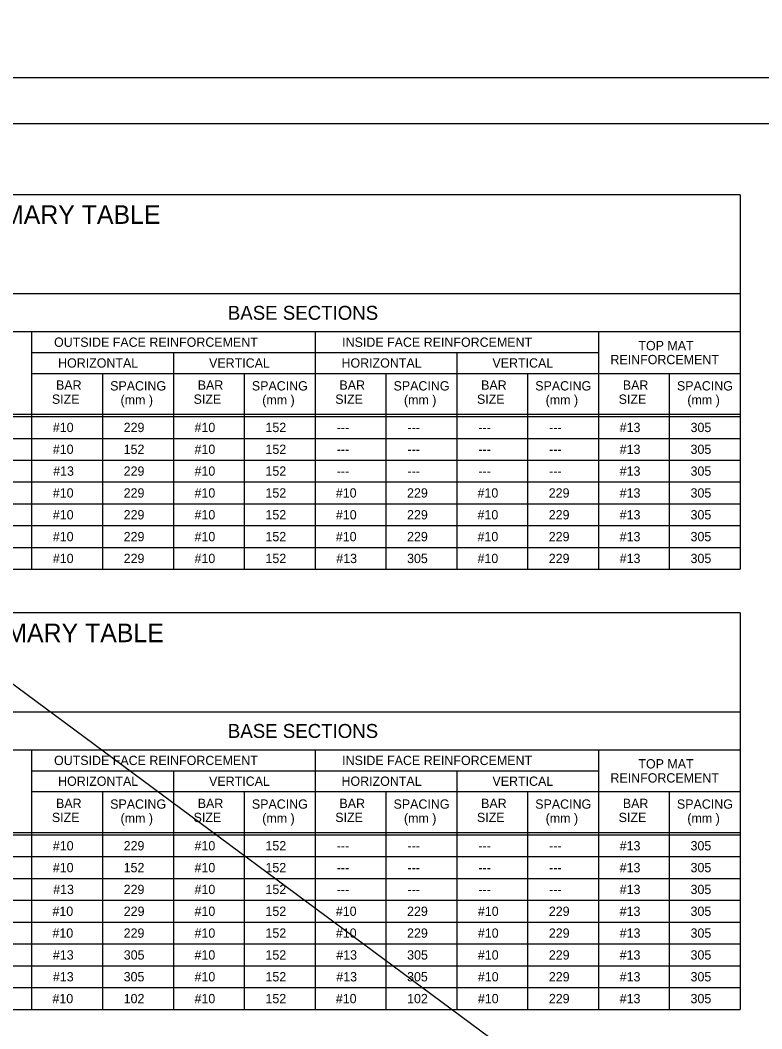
# Model space of a CAD drawing. Extents: x -6420 to 49575, y -4552 to 11624.
# Drawn here: x 35901 to 36686, y 4771 to 5838 of the extents above; entities that cross this region are included whole.
import ezdxf

# ---------------------------------------------------------------- set-up
doc = ezdxf.new("R2010")
doc.units = 0
doc.layers.add('1', color=7, linetype='Continuous')
doc.layers.add('4', color=7, linetype='Continuous')

msp = doc.modelspace()

# ---------------------------------------------------------------- linework, layer by layer
at = {"layer": '1'}
for p, q in [((34295.4, 6319.6), (48971.6, -4552.2)), ((36663.5, 5653.2), (34868.5, 5653.2)), ((36663.5, 5653.2), (36663.5, 5256.9)), ((36663.5, 5548.2), (34868.5, 5548.2)), ((36663.5, 5508.2), (35088.5, 5508.2)), ((35913.5, 5508.2), (35913.5, 5256.9)), ((36213.5, 5508.2), (36213.5, 5256.9)), ((36513.5, 5508.2), (36513.5, 5256.9)), ((35913.5, 5486.2), (36213.5, 5486.2)), ((36063.5, 5486.2), (36063.5, 5256.9)), ((36213.5, 5486.2), (36513.5, 5486.2)), ((36363.5, 5486.2), (36363.5, 5256.9)), ((35913.5, 5464.2), (36213.5, 5464.2)), ((35988.5, 5464.2), (35988.5, 5256.9)), ((36138.5, 5464.2), (36138.5, 5256.9)), ((36213.5, 5464.2), (36663.5, 5464.2)), ((36288.5, 5464.2), (36288.5, 5256.9)), ((36438.5, 5464.2), (36438.5, 5256.9)), ((36588.5, 5464.2), (36588.5, 5256.9)), ((34868.5, 5421), (36663.5, 5421)), ((34868.5, 5418.5), (36663.5, 5418.5)), ((34868.5, 5395.4), (36663.5, 5395.4)), ((34868.5, 5372.4), (36663.5, 5372.4)), ((34868.5, 5349.3), (36663.5, 5349.3)), ((34868.5, 5326.2), (36663.5, 5326.2)), ((34868.5, 5303.1), (36663.5, 5303.1)), ((34868.5, 5280), (36663.5, 5280)), ((34868.5, 5256.9), (36663.5, 5256.9)), ((36663.5, 5210.7), (34868.5, 5210.7)), ((36663.5, 5210.7), (36663.5, 4791.2)), ((36663.5, 5105.7), (34868.5, 5105.7)), ((36663.5, 5065.7), (35088.5, 5065.7)), ((35913.5, 5065.7), (35913.5, 4791.2)), ((36213.5, 5065.7), (36213.5, 4791.2)), ((36513.5, 5065.7), (36513.5, 4791.2)), ((35913.5, 5043.7), (36213.5, 5043.7)), ((36063.5, 5043.7), (36063.5, 4791.2)), ((36213.5, 5043.7), (36513.5, 5043.7)), ((36363.5, 5043.7), (36363.5, 4791.2)), ((35913.5, 5021.7), (36213.5, 5021.7)), ((35988.5, 5021.7), (35988.5, 4791.2)), ((36138.5, 5021.7), (36138.5, 4791.2)), ((36213.5, 5021.7), (36663.5, 5021.7)), ((36288.5, 5021.7), (36288.5, 4791.2)), ((36438.5, 5021.7), (36438.5, 4791.2)), ((36588.5, 5021.7), (36588.5, 4791.2)), ((34868.5, 4978.4), (36663.5, 4978.4)), ((34868.5, 4976), (36663.5, 4976)), ((34868.5, 4952.9), (36663.5, 4952.9)), ((34868.5, 4929.8), (36663.5, 4929.8)), ((34868.5, 4906.7), (36663.5, 4906.7)), ((34868.5, 4883.6), (36663.5, 4883.6)), ((34868.5, 4860.5), (36663.5, 4860.5)), ((34868.5, 4837.4), (36663.5, 4837.4)), ((34868.5, 4814.3), (36663.5, 4814.3)), ((34868.5, 4791.2), (36663.5, 4791.2))]:
    msp.add_line(p, q, dxfattribs=at)
msp.add_lwpolyline([(37372.3, 3877.8), (37372.3, 5728.2), (34793.5, 5728.2), (34793.5, 3877.8), (37372.3, 3877.8), (37372.3, 3964.3), (36716.1, 3964.3), (36716.1, 4176.5), (37372.3, 4176.5), (37372.3, 4271.5), (36716.1, 4271.5), (36716.1, 3877.8), (36974.7, 3877.8), (36974.7, 3964.3), (36974.7, 3877.8), (37227.3, 3877.8), (37227.3, 3964.3), (37227.3, 3923.9), (37372.3, 3923.9)], dxfattribs=at)
at = {"layer": '4'}
msp.add_lwpolyline([(34665.6, 5777.4), (37424.8, 5777.4), (37424.8, 3828.6), (34665.6, 3828.6)], close=True, dxfattribs=at)

# ---------------------------------------------------------------- texts
at = {"layer": '1'}
for s, height, p in [('CAST-IN-PLACE CONCRETE INLET BOX SUMMARY TABLE', 19.685, (35317.1, 5622.4)), ('BASE SECTIONS', 14.764, (36121.2, 5520.9)), ('OUTSIDE FACE REINFORCEMENT', 9.843, (35937.2, 5492.3)), ('INSIDE FACE REINFORCEMENT', 9.843, (36242.2, 5492.3)), ('TOP MAT', 9.84, (36555.8, 5488.7)), ('HORIZONTAL', 9.84, (35941.5, 5470.3)), ('VERTICAL', 9.84, (36101.3, 5470.3)), ('HORIZONTAL', 9.84, (36241.5, 5470.3)), ('VERTICAL', 9.84, (36401.3, 5470.3)), ('REINFORCEMENT', 9.843, (36526.2, 5473.9)), ('BAR', 9.84, (35939.3, 5446.9)), ('SPACING', 9.84, (35996.6, 5446.1)), ('BAR', 9.84, (36089.3, 5446.9)), ('SPACING', 9.84, (36146.6, 5446.1)), ('BAR', 9.84, (36239.3, 5446.9)), ('SPACING', 9.84, (36296.6, 5446.1)), ('BAR', 9.84, (36389.3, 5446.9)), ('SPACING', 9.84, (36446.6, 5446.1)), ('BAR', 9.84, (36539.3, 5446.9)), ('SPACING', 9.84, (36596.6, 5446.1)), ('SIZE', 9.84, (35934.9, 5432)), ('(mm )', 9.84, (36007.6, 5431.3)), ('SIZE', 9.84, (36084.9, 5432)), ('(mm )', 9.84, (36157.6, 5431.3)), ('SIZE', 9.84, (36234.9, 5432)), ('(mm )', 9.84, (36307.6, 5431.3)), ('SIZE', 9.84, (36384.9, 5432)), ('(mm )', 9.84, (36457.6, 5431.3)), ('SIZE', 9.84, (36534.9, 5432)), ('(mm )', 9.84, (36607.6, 5431.3)), ('#10', 9.84, (35935.9, 5402.1)), ('229', 9.84, (36010.9, 5402.1)), ('#10', 9.84, (36085.9, 5402.1)), ('152', 9.84, (36161, 5402.1)), ('#13', 9.84, (36536, 5402.1)), ('305', 9.84, (36611, 5402.1)), ('---', 9.84, (36236.4, 5402.1)), ('---', 9.84, (36311.4, 5402.1)), ('---', 9.84, (36386.4, 5402.1)), ('---', 9.84, (36461.4, 5402.1)), ('#10', 9.84, (35935.9, 5379)), ('152', 9.84, (36010.9, 5379)), ('#10', 9.84, (36085.9, 5379)), ('152', 9.84, (36161, 5379)), ('---', 9.84, (36236.4, 5379)), ('---', 9.84, (36311.4, 5379)), ('---', 9.84, (36386.4, 5379)), ('---', 9.84, (36461.4, 5379)), ('#13', 9.84, (36536, 5379)), ('305', 9.84, (36611, 5379)), ('#13', 9.84, (35936.3, 5355.9)), ('229', 9.84, (36010.9, 5355.9)), ('#10', 9.84, (36085.9, 5355.9)), ('152', 9.84, (36161, 5355.9)), ('---', 9.84, (36236.4, 5355.9)), ('---', 9.84, (36311.4, 5355.9)), ('---', 9.84, (36386.4, 5355.9)), ('---', 9.84, (36461.4, 5355.9)), ('#13', 9.84, (36536, 5355.9)), ('305', 9.84, (36611, 5355.9)), ('#10', 9.84, (35935.9, 5332.8)), ('229', 9.84, (36010.9, 5332.8)), ('#10', 9.84, (36085.9, 5332.8)), ('152', 9.84, (36161, 5332.8)), ('#10', 9.84, (36235.5, 5332.8)), ('229', 9.84, (36310.9, 5332.8)), ('#10', 9.84, (36385.5, 5332.8)), ('229', 9.84, (36460.9, 5332.8)), ('#13', 9.84, (36536, 5332.8)), ('305', 9.84, (36611, 5332.8)), ('#10', 9.84, (35935.9, 5309.7)), ('229', 9.84, (36010.9, 5309.7)), ('#10', 9.84, (36085.9, 5309.7)), ('152', 9.84, (36161, 5309.7)), ('#10', 9.84, (36235.6, 5309.7)), ('229', 9.84, (36310.9, 5309.7)), ('#10', 9.84, (36385.5, 5309.7)), ('229', 9.84, (36460.9, 5309.7)), ('#13', 9.84, (36536, 5309.7)), ('305', 9.84, (36611, 5309.7)), ('#10', 9.84, (35935.9, 5286.6)), ('229', 9.84, (36010.9, 5286.6)), ('#10', 9.84, (36085.9, 5286.6)), ('152', 9.84, (36161, 5286.6)), ('#10', 9.84, (36235.5, 5286.6)), ('229', 9.84, (36310.9, 5286.6)), ('#10', 9.84, (36385.5, 5286.6)), ('229', 9.84, (36460.9, 5286.6)), ('#13', 9.84, (36536, 5286.6)), ('305', 9.84, (36611, 5286.6)), ('#10', 9.84, (35935.9, 5263.5)), ('229', 9.84, (36010.9, 5263.5)), ('#10', 9.84, (36085.9, 5263.5)), ('152', 9.84, (36161, 5263.5)), ('#13', 9.84, (36236, 5263.5)), ('305', 9.84, (36310.9, 5263.5)), ('#10', 9.84, (36385.5, 5263.5)), ('229', 9.84, (36460.9, 5263.5)), ('#13', 9.84, (36536, 5263.5)), ('305', 9.84, (36611, 5263.5)), ('CAST-IN-PLACE CONCRETE INLET BOX SUMMARY TABLE', 19.685, (35320.6, 5179.8)), ('BASE SECTIONS', 14.764, (36121.2, 5078.5)), ('OUTSIDE FACE REINFORCEMENT', 9.843, (35937.2, 5049.8)), ('INSIDE FACE REINFORCEMENT', 9.843, (36242.2, 5049.8)), ('TOP MAT', 9.84, (36555.8, 5046.2)), ('HORIZONTAL', 9.84, (35941.5, 5027.8)), ('VERTICAL', 9.84, (36101.3, 5027.8)), ('HORIZONTAL', 9.84, (36241.5, 5027.8)), ('VERTICAL', 9.84, (36401.3, 5027.8)), ('REINFORCEMENT', 9.843, (36526.2, 5031.3)), ('BAR', 9.84, (35939.3, 5004.3)), ('SPACING', 9.84, (35996.6, 5003.6)), ('BAR', 9.84, (36089.3, 5004.3)), ('SPACING', 9.84, (36146.6, 5003.6)), ('BAR', 9.84, (36239.3, 5004.3)), ('SPACING', 9.84, (36296.6, 5003.6)), ('BAR', 9.84, (36389.3, 5004.3)), ('SPACING', 9.84, (36446.6, 5003.6)), ('BAR', 9.84, (36539.3, 5004.3)), ('SPACING', 9.84, (36596.6, 5003.6)), ('SIZE', 9.84, (35934.9, 4989.5)), ('(mm )', 9.84, (36007.6, 4988.7)), ('SIZE', 9.84, (36084.9, 4989.5)), ('(mm )', 9.84, (36157.6, 4988.7)), ('SIZE', 9.84, (36234.9, 4989.5)), ('(mm )', 9.84, (36307.6, 4988.7)), ('SIZE', 9.84, (36384.9, 4989.5)), ('(mm )', 9.84, (36457.6, 4988.7)), ('SIZE', 9.84, (36534.9, 4989.5)), ('(mm )', 9.84, (36607.6, 4988.7)), ('#10', 9.84, (35935.9, 4959.5)), ('229', 9.84, (36010.9, 4959.5)), ('#10', 9.84, (36085.9, 4959.5)), ('152', 9.84, (36161, 4959.5)), ('---', 9.84, (36236.4, 4959.5)), ('---', 9.84, (36311.4, 4959.5)), ('---', 9.84, (36386.4, 4959.5)), ('---', 9.84, (36461.4, 4959.5)), ('#13', 9.84, (36536, 4959.5)), ('305', 9.84, (36611, 4959.5)), ('#10', 9.84, (35935.9, 4936.4)), ('152', 9.84, (36010.9, 4936.4)), ('#10', 9.84, (36085.9, 4936.4)), ('152', 9.84, (36161, 4936.4)), ('#13', 9.84, (36536, 4936.4)), ('305', 9.84, (36611, 4936.4)), ('---', 9.84, (36236.4, 4936.4)), ('---', 9.84, (36311.4, 4936.4)), ('---', 9.84, (36386.4, 4936.4)), ('---', 9.84, (36461.4, 4936.4)), ('#13', 9.84, (35936.3, 4913.3)), ('229', 9.84, (36010.9, 4913.3)), ('#10', 9.84, (36085.9, 4913.3)), ('152', 9.84, (36161, 4913.3)), ('#13', 9.84, (36536, 4913.3)), ('305', 9.84, (36611, 4913.3)), ('---', 9.84, (36236.4, 4913.3)), ('---', 9.84, (36311.4, 4913.3)), ('---', 9.84, (36386.4, 4913.3)), ('---', 9.84, (36461.4, 4913.3)), ('#10', 9.84, (35935.5, 4890.2)), ('229', 9.84, (36011, 4890.2)), ('#10', 9.84, (36085.9, 4890.2)), ('152', 9.84, (36161, 4890.2)), ('#10', 9.84, (36235.5, 4890.2)), ('229', 9.84, (36310.9, 4890.2)), ('#10', 9.84, (36385.9, 4890.2)), ('229', 9.84, (36461, 4890.2)), ('#13', 9.84, (36536, 4890.2)), ('305', 9.84, (36611, 4890.2)), ('#10', 9.84, (35935.5, 4867.1)), ('229', 9.84, (36010.9, 4867.1)), ('#10', 9.84, (36085.9, 4867.1)), ('152', 9.84, (36161, 4867.1)), ('#10', 9.84, (36235.5, 4867.1)), ('229', 9.84, (36310.9, 4867.1)), ('#10', 9.84, (36385.9, 4867.1)), ('229', 9.84, (36461, 4867.1)), ('#13', 9.84, (36536, 4867.1)), ('305', 9.84, (36611, 4867.1)), ('#13', 9.84, (35936, 4844)), ('305', 9.84, (36011, 4844)), ('#10', 9.84, (36085.9, 4844)), ('152', 9.84, (36161, 4844)), ('#13', 9.84, (36236, 4844)), ('305', 9.84, (36311, 4844)), ('#10', 9.84, (36385.9, 4844)), ('229', 9.84, (36461, 4844)), ('#13', 9.84, (36536, 4844)), ('305', 9.84, (36611, 4844)), ('#13', 9.84, (35936, 4820.9)), ('305', 9.84, (36010.9, 4820.9)), ('#10', 9.84, (36085.9, 4820.9)), ('152', 9.84, (36161, 4820.9)), ('#13', 9.84, (36236, 4820.9)), ('305', 9.84, (36310.9, 4820.9)), ('#10', 9.84, (36385.9, 4820.9)), ('229', 9.84, (36461, 4820.9)), ('#13', 9.84, (36536, 4820.9)), ('305', 9.84, (36611, 4820.9)), ('#10', 9.84, (35935.5, 4797.8)), ('102', 9.84, (36010.9, 4797.8)), ('#10', 9.84, (36085.9, 4797.8)), ('152', 9.84, (36161, 4797.8)), ('#10', 9.84, (36235.5, 4797.8)), ('102', 9.84, (36310.9, 4797.8)), ('#10', 9.84, (36385.9, 4797.8)), ('229', 9.84, (36461, 4797.8)), ('#13', 9.84, (36536, 4797.8)), ('305', 9.84, (36611, 4797.8))]:
    msp.add_text(s, height=height, dxfattribs=at).set_placement(p)

doc.saveas('drawing.dxf')
